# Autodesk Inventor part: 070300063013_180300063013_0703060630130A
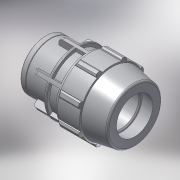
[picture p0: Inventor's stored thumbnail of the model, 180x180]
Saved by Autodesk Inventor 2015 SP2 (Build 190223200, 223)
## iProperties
Created: 2017-02
Part Number: 070300063013_180300063013_0703060630130A
Material: PVC-Piping
Description: PLASSON FEMALE ADAPTOR 63-1.1/4"
Document SubType Name: Modeling
Designer: KIM
Mass: 92.6774 g
Surface Area: 199.44 cm^2
Volume: 66.1981 cm^3
Density: 1.4 g/cm^3
Appearance: Smooth - White
Author: KIM
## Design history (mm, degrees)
derived "07030.ipt"
feature "Solid1::07030.ipt"
tag "TaggingFeature1"
body "Solid1"
other parameters: "d2" = 63, "d4" = 19.85714, "d5" = 34.75, "d7" = 113, "d9" = 19.85714, "d11" = 3.97143, "d12" = 90.4, "d13" = 120 deg, "d14" = 88.2, "d15" = 10 deg, "d16" = 101.7, "d18" = 3.15, "d19" = 35 deg, "d20" = 17.5 deg, "d21" = 105.09, "d23" = 0, "d25" = 360 deg, "d27" = 2.26, "d34" = 5.65, "d35" = 41.7, "d36" = 0, "d42" = 34.75, "d43" = 3.39, "d46" = 1.89, "d51" = 139, "d53" = 1.26, "d55" = 360 deg, "d61" = 25, "d62" = 50.4, "d63" = 38.952, "d64" = 46.33333, "d65" = 5.65, "d66" = 0.5, "d67" = 1, "d68" = 7.5, "d69" = 81.36, "d70" = 2.825, "d_" = 63, "E_" = 113, "H_" = 139, "l_2" = 25, "Rp_" = 38.952
